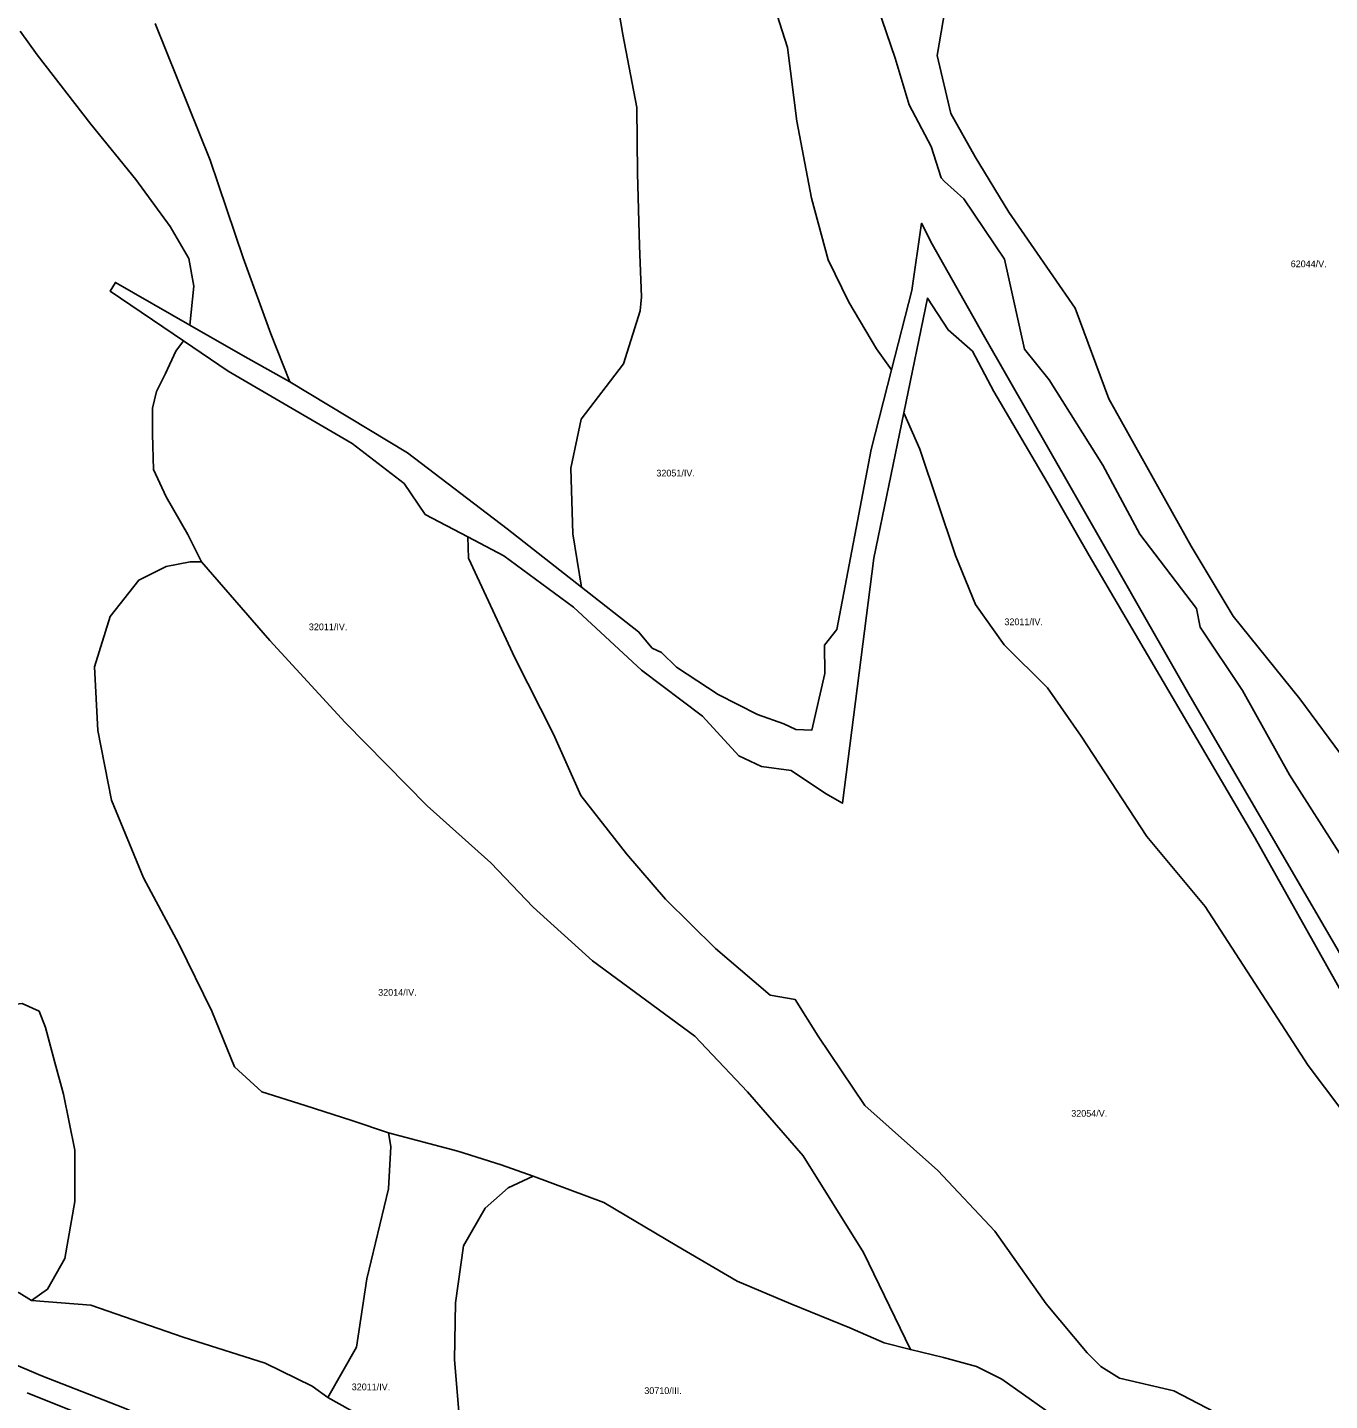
# Model space of a CAD drawing. Extents: x -521621 to -516761, y -1190184 to -1184927.
# Drawn here: x -520002 to -519227, y -1189352 to -1188534 of the extents above; entities that cross this region are included whole.
import ezdxf

# ---------------------------------------------------------------- set-up
doc = ezdxf.new("R2010")
doc.units = 0
doc.layers.add('BPEJ_s', color=7, linetype='Continuous')

msp = doc.modelspace()

# ---------------------------------------------------------------- linework, layer by layer
at = {"layer": 'BPEJ_s'}
for p, q in [((-519506.34, -1188491.18), (-519485.41, -1188552.38)), ((-519549.61, -1188546.12), (-519558.88, -1188516.72)), ((-519926.01, -1188531.81), (-519893.15, -1188613.14)), ((-519996.18, -1188550.48), (-520006.43, -1188536.42)), ((-519543.94, -1188589.95), (-519549.61, -1188546.12)), ((-519964.21, -1188591.81), (-519996.18, -1188550.48)), ((-519485.41, -1188552.38), (-519477.23, -1188580.23)), ((-519477.23, -1188580.23), (-519463.97, -1188605.01)), ((-519535.18, -1188635.85), (-519543.94, -1188589.95)), ((-519937.56, -1188624.69), (-519964.21, -1188591.81)), ((-519463.97, -1188605.01), (-519458.05, -1188623.65)), ((-519893.15, -1188613.14), (-519873.61, -1188671.36)), ((-519458.05, -1188623.65), (-519456.03, -1188625.92)), ((-519917.13, -1188652.69), (-519937.56, -1188624.69)), ((-519456.03, -1188625.92), (-519444.65, -1188636.17)), ((-519525.38, -1188672.46), (-519535.18, -1188635.85)), ((-519444.65, -1188636.17), (-519420.39, -1188672.15)), ((-519906.03, -1188671.8), (-519917.13, -1188652.69)), ((-519469.71, -1188650.74), (-519475.48, -1188690.82)), ((-519463.45, -1188663.24), (-519469.71, -1188650.74)), ((-519432.23, -1188718.32), (-519463.45, -1188663.24)), ((-519902.92, -1188688.24), (-519906.03, -1188671.8)), ((-519873.61, -1188671.36), (-519857.17, -1188716.69)), ((-519513.01, -1188697.73), (-519525.38, -1188672.46)), ((-519420.39, -1188672.15), (-519408.57, -1188725.66)), ((-519905.3, -1188711.46), (-519902.92, -1188688.24)), ((-519475.48, -1188690.82), (-519487.56, -1188738.03)), ((-519496.52, -1188725.57), (-519513.01, -1188697.73)), ((-519873.72, -1188729.57), (-519905.3, -1188711.46)), ((-519857.17, -1188716.69), (-519845.83, -1188745.1)), ((-519379.9, -1188809.98), (-519432.23, -1188718.32)), ((-519845.83, -1188745.1), (-519873.72, -1188729.57)), ((-519487.56, -1188738.03), (-519496.52, -1188725.57)), ((-519408.57, -1188725.66), (-519393.72, -1188743.94)), ((-519393.72, -1188743.94), (-519361.83, -1188794.75)), ((-519361.83, -1188794.75), (-519339.91, -1188835.88)), ((-519310.72, -1188931.27), (-519379.9, -1188809.98)), ((-519339.91, -1188835.88), (-519306.15, -1188880.18)), ((-519306.15, -1188880.18), (-519303.92, -1188891.31)), ((-519303.92, -1188891.31), (-519278.8, -1188929.02)), ((-519204.35, -1189113.86), (-519310.72, -1188931.27)), ((-519278.8, -1188929.02), (-519250.65, -1188979.3)), ((-519250.65, -1188979.3), (-519219.5, -1189028.08))]:
    msp.add_line(p, q, dxfattribs=at)
for points in [[(-519216.99, -1188971.26), (-519244.62, -1188934.05), (-519284.32, -1188884.77), (-519309.17, -1188843.09), (-519358.26, -1188755.31), (-519378.38, -1188701.36), (-519417.81, -1188644.18), (-519437.93, -1188611.17), (-519452.42, -1188585.4), (-519460.46, -1188550.77), (-519452.42, -1188503.26), (-519450, -1188446.89), (-519458.85, -1188400.99), (-519476.56, -1188356.7), (-519503.12, -1188316.44), (-519531.29, -1188296.3), (-519557.84, -1188282.61), (-519586.01, -1188266.51), (-519605.33, -1188251.21), (-519610.15, -1188244.76), (-519618.2, -1188203.69), (-519639.13, -1188151.35), (-519646.37, -1188085.32)], [(-519219.5, -1189028.08), (-519250.65, -1188979.3), (-519278.8, -1188929.02), (-519303.92, -1188891.31), (-519306.15, -1188880.18), (-519339.91, -1188835.88), (-519361.83, -1188794.75), (-519393.72, -1188743.94), (-519408.57, -1188725.66), (-519420.39, -1188672.15), (-519444.65, -1188636.17), (-519456.03, -1188625.92), (-519458.05, -1188623.65), (-519463.97, -1188605.01), (-519477.23, -1188580.23), (-519485.41, -1188552.38), (-519506.34, -1188491.18)], [(-519452.42, -1188503.26), (-519460.46, -1188550.77), (-519452.42, -1188585.4), (-519437.93, -1188611.17), (-519417.81, -1188644.18), (-519378.38, -1188701.36), (-519358.26, -1188755.31), (-519309.17, -1188843.09), (-519284.32, -1188884.77), (-519244.62, -1188934.05), (-519216.99, -1188971.26)], [(-519651.13, -1188517.24), (-519647.53, -1188538.38), (-519639.28, -1188581.7), (-519638.76, -1188620.89), (-519637.73, -1188664.21), (-519636.44, -1188694.47), (-519637.33, -1188702.91), (-519647.1, -1188734.46), (-519672.42, -1188767.35), (-519678.63, -1188796.68), (-519677.3, -1188835.79), (-519672.1, -1188867.48), (-519716.52, -1188832.7), (-519775.82, -1188787.54), (-519845.83, -1188745.1), (-519857.17, -1188716.69), (-519873.61, -1188671.36), (-519893.15, -1188613.14), (-519926.01, -1188531.81)], [(-519558.88, -1188516.72), (-519549.61, -1188546.12), (-519543.94, -1188589.95), (-519535.18, -1188635.85), (-519525.38, -1188672.46), (-519513.01, -1188697.73), (-519496.52, -1188725.57), (-519487.56, -1188738.03), (-519499.71, -1188785.52), (-519520.18, -1188892.7), (-519527.55, -1188902.09), (-519527.39, -1188918.95), (-519535.05, -1188952.61), (-519544.57, -1188952.32), (-519551.65, -1188948.86), (-519567.39, -1188943.37), (-519590.89, -1188931.4), (-519615.73, -1188915.22), (-519624.63, -1188906.31), (-519630.11, -1188903.71), (-519638.2, -1188894.03), (-519672.1, -1188867.48), (-519677.3, -1188835.79), (-519678.63, -1188796.68), (-519672.42, -1188767.35), (-519647.1, -1188734.46), (-519637.33, -1188702.91), (-519636.44, -1188694.47), (-519637.73, -1188664.21), (-519638.76, -1188620.89), (-519639.28, -1188581.7), (-519647.53, -1188538.38), (-519651.13, -1188517.24)], [(-520006.43, -1188536.42), (-519996.18, -1188550.48), (-519964.21, -1188591.81), (-519937.56, -1188624.69), (-519917.13, -1188652.69), (-519906.03, -1188671.8), (-519902.92, -1188688.24), (-519905.3, -1188711.46), (-519949.65, -1188686.01), (-519952.77, -1188691.15), (-519909.2, -1188720.78), (-519913.58, -1188726.91), (-519919.8, -1188740.24), (-519925.12, -1188750.9), (-519927.59, -1188760.8), (-519927.59, -1188776.42), (-519926.91, -1188797.46), (-519919.44, -1188813.76), (-519906.55, -1188836.16), (-519898.41, -1188852.45), (-519905.2, -1188852.45), (-519919.44, -1188855.17), (-519935.73, -1188863.31), (-519952.69, -1188885.04), (-519962.19, -1188914.91), (-519960.15, -1188952.92), (-519952.01, -1188994.33), (-519933.01, -1189040.5), (-519911.98, -1189079.87), (-519892.3, -1189119.93), (-519878.74, -1189153.19), (-519862.45, -1189168.12), (-519836.67, -1189176.27), (-519808.86, -1189185.1), (-519787.14, -1189192.56), (-519785.79, -1189200.71), (-519787.14, -1189225.83), (-519800.04, -1189279.46), (-519806.14, -1189320.19), (-519823.1, -1189350.06), (-519832.6, -1189343.27), (-519860.42, -1189329.7), (-519909.27, -1189314.08), (-519964.22, -1189295.07), (-519999.5, -1189292.36), (-519990, -1189285.57), (-519979.83, -1189267.24), (-519973.72, -1189233.3), (-519973.72, -1189202.75), (-519980.5, -1189169.48), (-519985.7, -1189150.52), (-519991.34, -1189129.81), (-519995.11, -1189120.08), (-520005.14, -1189115.37)], [(-519209.47, -1189126.94), (-519271.12, -1189017.05), (-519370.06, -1188848.53), (-519394.74, -1188805.26), (-519426.75, -1188750.88), (-519439.41, -1188726.94), (-519454, -1188714.22), (-519466.31, -1188695.34), (-519480.34, -1188763.64), (-519498.15, -1188850.28), (-519516.83, -1188996.16), (-519526.93, -1188990.29), (-519547.43, -1188976.71), (-519565.05, -1188974.25), (-519578.62, -1188967.9), (-519600.08, -1188944.39), (-519636.46, -1188916.94), (-519676.87, -1188879.43), (-519718.51, -1188848.73), (-519739.95, -1188837.47), (-519765.29, -1188824.17), (-519777.81, -1188805.75), (-519808.71, -1188781.91), (-519882.55, -1188738.91), (-519909.2, -1188720.78), (-519952.77, -1188691.15), (-519949.65, -1188686.01), (-519905.3, -1188711.46), (-519873.72, -1188729.57), (-519845.83, -1188745.1), (-519775.82, -1188787.54), (-519716.52, -1188832.7), (-519672.1, -1188867.48), (-519638.2, -1188894.03), (-519630.11, -1188903.71), (-519624.63, -1188906.31), (-519615.73, -1188915.22), (-519590.89, -1188931.4), (-519567.39, -1188943.37), (-519551.65, -1188948.86), (-519544.57, -1188952.32), (-519535.05, -1188952.61), (-519527.39, -1188918.95), (-519527.55, -1188902.09), (-519520.18, -1188892.7), (-519499.71, -1188785.52), (-519487.56, -1188738.03), (-519475.48, -1188690.82), (-519469.71, -1188650.74), (-519463.45, -1188663.24), (-519432.23, -1188718.32), (-519379.9, -1188809.98), (-519310.72, -1188931.27), (-519204.35, -1189113.86)], [(-519210.45, -1189190.99), (-519239.6, -1189152.28), (-519300.91, -1189057.74), (-519335.58, -1189016.01), (-519374.78, -1188956.17), (-519394.88, -1188927.51), (-519420.51, -1188901.87), (-519437.59, -1188877.73), (-519449.65, -1188848.57), (-519470.76, -1188785.21), (-519480.34, -1188763.64), (-519466.31, -1188695.34), (-519454, -1188714.22), (-519439.41, -1188726.94), (-519426.75, -1188750.88), (-519394.74, -1188805.26), (-519370.06, -1188848.53), (-519271.12, -1189017.05), (-519209.47, -1189126.94)], [(-519383.19, -1189366.6), (-519421.98, -1189339.11), (-519437.06, -1189331.73), (-519456.74, -1189326.3), (-519476.41, -1189321.55), (-519504.23, -1189263.84), (-519540.19, -1189206.14), (-519573.43, -1189168.12), (-519604.64, -1189134.86), (-519665.7, -1189090.06), (-519700.98, -1189058.15), (-519726.08, -1189031.67), (-519764.08, -1188997.73), (-519812.93, -1188948.17), (-519857.7, -1188899.29), (-519898.41, -1188852.45), (-519906.55, -1188836.16), (-519919.44, -1188813.76), (-519926.91, -1188797.46), (-519927.59, -1188776.42), (-519927.59, -1188760.8), (-519925.12, -1188750.9), (-519919.8, -1188740.24), (-519913.58, -1188726.91), (-519909.2, -1188720.78), (-519882.55, -1188738.91), (-519808.71, -1188781.91), (-519777.81, -1188805.75), (-519765.29, -1188824.17), (-519739.95, -1188837.47), (-519739.36, -1188850.12), (-519711.84, -1188909.48), (-519688.77, -1188954.96), (-519672.49, -1188991.62), (-519645.35, -1189026.24), (-519622.28, -1189053.4), (-519592.43, -1189082.59), (-519569.36, -1189102.27), (-519559.86, -1189110.42), (-519544.94, -1189113.14), (-519531.37, -1189134.86), (-519503.55, -1189176.27), (-519460.13, -1189214.97), (-519426.21, -1189250.95), (-519395.68, -1189294.39), (-519371.25, -1189323.58), (-519363.11, -1189331.73), (-519351.95, -1189338.57), (-519319.63, -1189346.12), (-519285.69, -1189363.91)], [(-519285.69, -1189363.91), (-519319.63, -1189346.12), (-519351.95, -1189338.57), (-519363.11, -1189331.73), (-519371.25, -1189323.58), (-519395.68, -1189294.39), (-519426.21, -1189250.95), (-519460.13, -1189214.97), (-519503.55, -1189176.27), (-519531.37, -1189134.86), (-519544.94, -1189113.14), (-519559.86, -1189110.42), (-519569.36, -1189102.27), (-519592.43, -1189082.59), (-519622.28, -1189053.4), (-519645.35, -1189026.24), (-519672.49, -1188991.62), (-519688.77, -1188954.96), (-519711.84, -1188909.48), (-519739.36, -1188850.12), (-519739.95, -1188837.47), (-519718.51, -1188848.73), (-519676.87, -1188879.43), (-519636.46, -1188916.94), (-519600.08, -1188944.39), (-519578.62, -1188967.9), (-519565.05, -1188974.25), (-519547.43, -1188976.71), (-519526.93, -1188990.29), (-519516.83, -1188996.16), (-519498.15, -1188850.28), (-519480.34, -1188763.64), (-519470.76, -1188785.21), (-519449.65, -1188848.57), (-519437.59, -1188877.73), (-519420.51, -1188901.87), (-519394.88, -1188927.51), (-519374.78, -1188956.17), (-519335.58, -1189016.01), (-519300.91, -1189057.74), (-519239.6, -1189152.28), (-519210.45, -1189190.99)], [(-519745.08, -1189360.92), (-519747.79, -1189327.66), (-519747.12, -1189293.72), (-519742.37, -1189259.77), (-519729.48, -1189237.37), (-519715.91, -1189225.15), (-519700.98, -1189218.36), (-519658.92, -1189233.98), (-519615.5, -1189259.77), (-519579.54, -1189280.82), (-519547.65, -1189294.39), (-519512.37, -1189308.65), (-519492.02, -1189317.48), (-519476.41, -1189321.55), (-519456.74, -1189326.3), (-519437.06, -1189331.73), (-519421.98, -1189339.11), (-519383.19, -1189366.6)], [(-520006.99, -1189287.86), (-519999.5, -1189292.36), (-519964.22, -1189295.07), (-519909.27, -1189314.08), (-519860.42, -1189329.7), (-519832.6, -1189343.27), (-519823.1, -1189350.06), (-519784.43, -1189371.79), (-519748.47, -1189384), (-519736.94, -1189388.76), (-519715.23, -1189396.9), (-519701.66, -1189406.41), (-519698.2, -1189413.9), (-519684.99, -1189438.94), (-519683.25, -1189455.63), (-519683.56, -1189464.86), (-519700.98, -1189457.42), (-519794.24, -1189421.2), (-519944.22, -1189356.48), (-519993.99, -1189336.93), (-520071.75, -1189303.77)], [(-520071.75, -1189303.77), (-519993.99, -1189336.93), (-519944.22, -1189356.48)], [(-519948.89, -1189368.76), (-520002.08, -1189347.37)], [(-520002.08, -1189347.37), (-519948.89, -1189368.76)]]:
    msp.add_lwpolyline(points, dxfattribs=at)
for points in [[(-519898.41, -1188852.45), (-519857.7, -1188899.29), (-519812.93, -1188948.17), (-519764.08, -1188997.73), (-519726.08, -1189031.67), (-519700.98, -1189058.15), (-519665.7, -1189090.06), (-519604.64, -1189134.86), (-519573.43, -1189168.12), (-519540.19, -1189206.14), (-519504.23, -1189263.84), (-519476.41, -1189321.55), (-519492.02, -1189317.48), (-519512.37, -1189308.65), (-519547.65, -1189294.39), (-519579.54, -1189280.82), (-519615.5, -1189259.77), (-519658.92, -1189233.98), (-519700.98, -1189218.36), (-519719.98, -1189211.57), (-519745.76, -1189203.43), (-519787.14, -1189192.56), (-519808.86, -1189185.1), (-519836.67, -1189176.27), (-519862.45, -1189168.12), (-519878.74, -1189153.19), (-519892.3, -1189119.93), (-519911.98, -1189079.87), (-519933.01, -1189040.5), (-519952.01, -1188994.33), (-519960.15, -1188952.92), (-519962.19, -1188914.91), (-519952.69, -1188885.04), (-519935.73, -1188863.31), (-519919.44, -1188855.17), (-519905.2, -1188852.45)], [(-520035.98, -1189267.06), (-520042.62, -1189238.63), (-520042.62, -1189201.15), (-520039.43, -1189191.85), (-520036.82, -1189174.06), (-520033.06, -1189155.86), (-520026.79, -1189137.03), (-520021.14, -1189123.22), (-520012.36, -1189116.31), (-520005.14, -1189115.37), (-519995.11, -1189120.08), (-519991.34, -1189129.81), (-519985.7, -1189150.52), (-519980.5, -1189169.48), (-519973.72, -1189202.75), (-519973.72, -1189233.3), (-519979.83, -1189267.24), (-519990, -1189285.57), (-519999.5, -1189292.36), (-520006.99, -1189287.86), (-520014.94, -1189284.68), (-520022.89, -1189280.37), (-520029.93, -1189275.14)], [(-519823.1, -1189350.06), (-519806.14, -1189320.19), (-519800.04, -1189279.46), (-519787.14, -1189225.83), (-519785.79, -1189200.71), (-519787.14, -1189192.56), (-519745.76, -1189203.43), (-519719.98, -1189211.57), (-519700.98, -1189218.36), (-519715.91, -1189225.15), (-519729.48, -1189237.37), (-519742.37, -1189259.77), (-519747.12, -1189293.72), (-519747.79, -1189327.66), (-519745.08, -1189360.92), (-519736.94, -1189388.76), (-519748.47, -1189384), (-519784.43, -1189371.79)]]:
    msp.add_lwpolyline(points, close=True, dxfattribs=at)

# ---------------------------------------------------------------- texts
for s, p in [('62044/V.', (-519250.02, -1188676.92)), ('32051/IV.', (-519627.62, -1188801.54)), ('32011/IV.', (-519834.49, -1188893.12)), ('32011/IV.', (-519420.43, -1188890.12)), ('32014/IV.', (-519793.2, -1189110.82)), ('32054/V.', (-519380.64, -1189182.89)), ('32011/IV.', (-519808.97, -1189345.79)), ('30710/III.', (-519634.81, -1189348.04))]:
    msp.add_text(s, height=4, dxfattribs=at).set_placement(p)

doc.saveas('drawing.dxf')
